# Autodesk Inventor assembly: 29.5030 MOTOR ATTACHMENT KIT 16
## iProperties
Created: 2007-07
Part Number: 29.5030 MOTOR ATTACHMENT KIT 16
Document SubType Name: Assembly
Designer: Andy Moles
Author: Andy Moles
